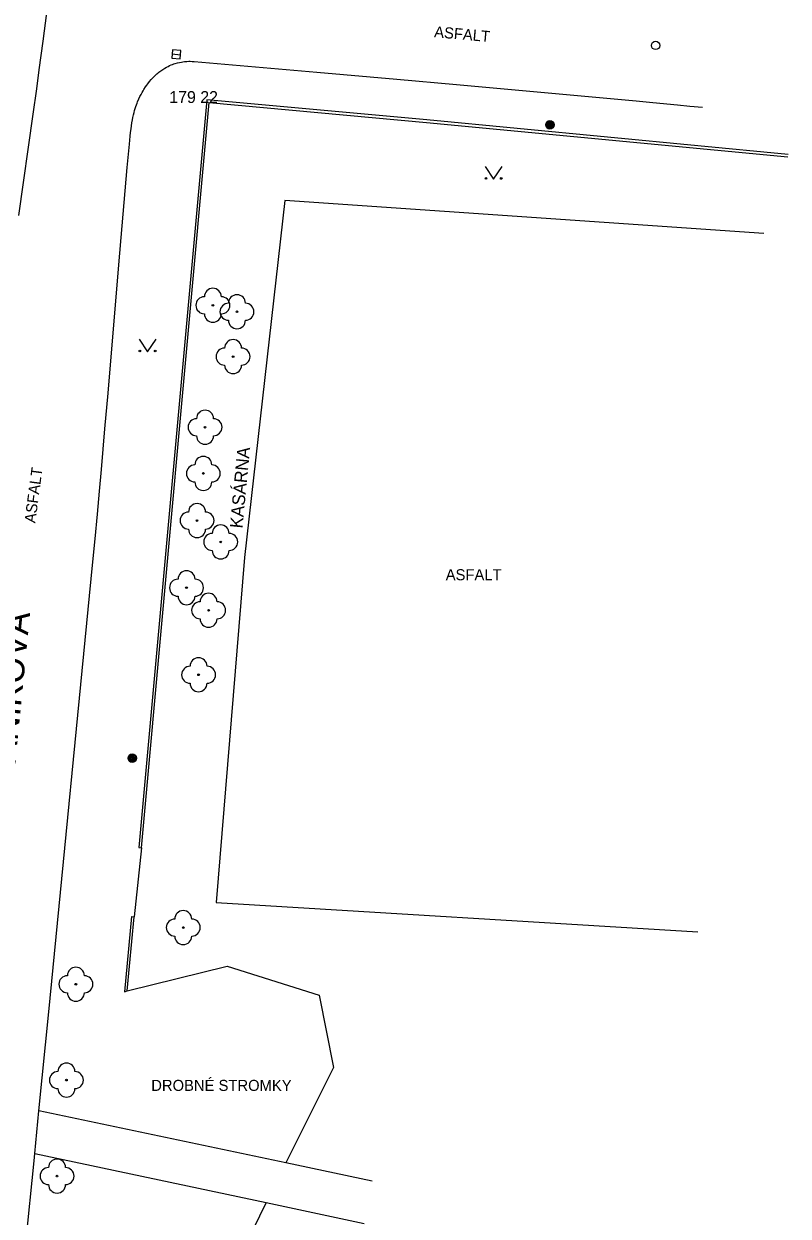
# Model space of a CAD drawing. Extents: x -538441 to -536770, y -1181008 to -1179809.
# Drawn here: x -537087.2 to -537042.3, y -1180849.4 to -1180779.3 of the extents above; entities that cross this region are included whole.
import ezdxf

# ---------------------------------------------------------------- set-up
doc = ezdxf.new("R2010")
doc.units = 0
for name, color, linetype in [('Vrstva 10', 7, 'Continuous'), ('Vrstva 11', 7, 'Continuous'), ('Vrstva 21', 7, 'Continuous'), ('Vrstva 22', 7, 'Continuous'), ('Vrstva 25', 7, 'Continuous'), ('Vrstva 27', 7, 'Continuous'), ('Vrstva 28', 7, 'Continuous'), ('Vrstva 36', 7, 'Continuous'), ('Vrstva 4', 7, 'Continuous'), ('Vrstva 40', 7, 'Continuous'), ('Vrstva 41', 7, 'Continuous'), ('Vrstva 49', 7, 'Continuous'), ('Vrstva 7', 7, 'Continuous'), ('Vrstva 8', 7, 'Continuous')]:
    doc.layers.add(name, color=color, linetype=linetype)

msp = doc.modelspace()

# ---------------------------------------------------------------- linework, layer by layer
at = {"layer": 'Vrstva 10'}
for p, q in [((-537073.585, -1180781.803), (-537069.981, -1180782.118)), ((-537061.759, -1180782.852), (-537051.19, -1180783.81)), ((-537087.518, -1180790.548), (-537086.674, -1180784.586)), ((-537082.266, -1180801.001), (-537081.65, -1180793.68)), ((-537082.445, -1180803.092), (-537082.266, -1180801.001)), ((-537085.756, -1180837.388), (-537083.18, -1180811.11)), ((-537087.117, -1180851.151), (-537086.62, -1180846.146))]:
    msp.add_line(p, q, dxfattribs=at)
for points in [[(-537086.674, -1180784.586), (-537086.465, -1180783.095), (-537086.31, -1180781.977), (-537086.082, -1180780.299), (-537085.86, -1180778.62)], [(-537080.526, -1180783.859), (-537080.455, -1180783.693), (-537080.387, -1180783.548), (-537080.322, -1180783.421), (-537080.261, -1180783.311), (-537080.205, -1180783.215), (-537080.153, -1180783.131), (-537080.057, -1180782.985), (-537079.98, -1180782.875), (-537079.919, -1180782.794), (-537079.822, -1180782.672), (-537079.72, -1180782.55), (-537079.653, -1180782.475), (-537079.587, -1180782.405), (-537079.521, -1180782.339), (-537079.458, -1180782.278), (-537079.395, -1180782.222), (-537079.333, -1180782.169), (-537079.273, -1180782.119), (-537079.154, -1180782.029), (-537079.041, -1180781.951), (-537078.934, -1180781.884), (-537078.831, -1180781.826), (-537078.734, -1180781.775), (-537078.642, -1180781.731), (-537078.555, -1180781.694), (-537078.473, -1180781.661), (-537078.395, -1180781.633), (-537078.322, -1180781.609), (-537078.183, -1180781.57), (-537078.061, -1180781.541), (-537077.954, -1180781.521), (-537077.859, -1180781.506), (-537077.776, -1180781.496), (-537077.63, -1180781.484), (-537077.521, -1180781.479), (-537077.438, -1180781.478), (-537077.314, -1180781.482), (-537077.19, -1180781.49), (-537073.585, -1180781.803)], [(-537069.981, -1180782.118), (-537065.283, -1180782.535), (-537061.759, -1180782.852)], [(-537081.65, -1180793.68), (-537081.495, -1180791.85), (-537081.257, -1180789.105), (-537081.135, -1180787.732), (-537081.01, -1180786.36), (-537080.987, -1180786.11), (-537080.964, -1180785.878), (-537080.94, -1180785.66), (-537080.915, -1180785.458), (-537080.889, -1180785.269), (-537080.861, -1180785.093), (-537080.831, -1180784.928), (-537080.801, -1180784.775), (-537080.768, -1180784.631), (-537080.735, -1180784.497), (-537080.701, -1180784.372), (-537080.666, -1180784.255), (-537080.631, -1180784.146), (-537080.596, -1180784.044), (-537080.561, -1180783.949), (-537080.526, -1180783.859)], [(-537051.19, -1180783.81), (-537050.218, -1180783.902), (-537048.759, -1180784.043), (-537048.03, -1180784.11), (-537047.3, -1180784.17)], [(-537083.18, -1180811.11), (-537083.03, -1180809.564), (-537082.894, -1180808.115), (-537082.769, -1180806.756), (-537082.655, -1180805.482), (-537082.445, -1180803.092)], [(-537086.62, -1180846.146), (-537086.578, -1180845.724), (-537086.33, -1180843.208), (-537085.756, -1180837.388)]]:
    msp.add_lwpolyline(points, dxfattribs=at)
at = {"layer": 'Vrstva 11'}
for p, q in [((-537071.86, -1180789.67), (-537074.24, -1180810.67)), ((-537043.68, -1180791.6), (-537071.86, -1180789.67)), ((-537074.24, -1180810.67), (-537075.91, -1180830.96)), ((-537075.91, -1180830.96), (-537047.56, -1180832.69))]:
    msp.add_line(p, q, dxfattribs=at)
for points in [[(-537066.72, -1180847.35), (-537071.798, -1180846.277), (-537086.33, -1180843.208)], [(-537086.578, -1180845.724), (-537072.957, -1180848.609), (-537067.19, -1180849.83)]]:
    msp.add_lwpolyline(points, dxfattribs=at)
at = {"layer": 'Vrstva 21'}
for p, q in [((-537081.148, -1180836.157), (-537075.25, -1180834.71)), ((-537075.25, -1180834.71), (-537069.84, -1180836.4)), ((-537069.84, -1180836.4), (-537069.01, -1180840.67)), ((-537069.01, -1180840.67), (-537071.798, -1180846.277)), ((-537072.957, -1180848.609), (-537078.12, -1180858.99))]:
    msp.add_line(p, q, dxfattribs=at)
at = {"layer": 'Vrstva 22'}
for centre in [(-537076.1, -1180795.83), (-537074.68, -1180796.21), (-537074.91, -1180798.85), (-537076.56, -1180803), (-537076.66, -1180805.72), (-537077.03, -1180808.49), (-537075.64, -1180809.75), (-537077.65, -1180812.44), (-537076.35, -1180813.77), (-537076.94, -1180817.56), (-537077.84, -1180832.43), (-537084.16, -1180835.76), (-537084.713, -1180841.403), (-537085.267, -1180847.047)]:
    msp.add_circle(centre, 0.05, dxfattribs=at)
for centre, start, end in [((-537076.1, -1180795.33), 0, 180), ((-537076.6, -1180795.83), 90, 270), ((-537075.6, -1180795.83), 270, 90), ((-537074.68, -1180795.71), 0, 180), ((-537075.18, -1180796.21), 90, 270), ((-537074.18, -1180796.21), 270, 90), ((-537076.1, -1180796.33), 180, 0), ((-537074.68, -1180796.71), 180, 0), ((-537075.41, -1180798.85), 90, 270), ((-537074.91, -1180798.35), 0, 180), ((-537074.41, -1180798.85), 270, 90), ((-537074.91, -1180799.35), 180, 0), ((-537077.06, -1180803), 90, 270), ((-537076.56, -1180802.5), 0, 180), ((-537076.06, -1180803), 270, 90), ((-537076.56, -1180803.5), 180, 0), ((-537077.16, -1180805.72), 90, 270), ((-537076.66, -1180805.22), 0, 180), ((-537076.16, -1180805.72), 270, 90), ((-537076.66, -1180806.22), 180, 0), ((-537077.03, -1180807.99), 0, 180), ((-537077.53, -1180808.49), 90, 270), ((-537076.53, -1180808.49), 270, 90), ((-537075.64, -1180809.25), 0, 180), ((-537077.03, -1180808.99), 180, 0), ((-537076.14, -1180809.75), 90, 270), ((-537075.14, -1180809.75), 270, 90), ((-537075.64, -1180810.25), 180, 0), ((-537077.65, -1180811.94), 0, 180), ((-537078.15, -1180812.44), 90, 270), ((-537077.15, -1180812.44), 270, 90), ((-537077.65, -1180812.94), 180, 0), ((-537076.35, -1180813.27), 0, 180), ((-537076.85, -1180813.77), 90, 270), ((-537075.85, -1180813.77), 270, 90), ((-537076.35, -1180814.27), 180, 0), ((-537076.94, -1180817.06), 0, 180), ((-537077.44, -1180817.56), 90, 270), ((-537076.44, -1180817.56), 270, 90), ((-537076.94, -1180818.06), 180, 0), ((-537078.34, -1180832.43), 90, 270), ((-537077.84, -1180831.93), 0, 180), ((-537077.34, -1180832.43), 270, 90), ((-537077.84, -1180832.93), 180, 0), ((-537084.16, -1180835.26), 0, 180), ((-537084.66, -1180835.76), 90, 270), ((-537083.66, -1180835.76), 270, 90), ((-537084.16, -1180836.26), 180, 0), ((-537084.713, -1180840.903), 0, 180), ((-537085.213, -1180841.403), 90, 270), ((-537084.213, -1180841.403), 270, 90), ((-537084.713, -1180841.903), 180, 0), ((-537085.267, -1180846.547), 0, 180), ((-537085.767, -1180847.047), 90, 270), ((-537084.767, -1180847.047), 270, 90), ((-537085.267, -1180847.547), 180, 0)]:
    msp.add_arc(centre, 0.5, start, end, dxfattribs=at)
at = {"layer": 'Vrstva 25'}
for centre, radius in [((-537056.27, -1180785.21), 0.25), ((-537056.27, -1180785.21), 0.2), ((-537056.27, -1180785.21), 0.15), ((-537056.27, -1180785.21), 0.1), ((-537056.27, -1180785.21), 0.05), ((-537080.84, -1180822.47), 0.25), ((-537080.84, -1180822.47), 0.2), ((-537080.84, -1180822.47), 0.15), ((-537080.84, -1180822.47), 0.1), ((-537080.84, -1180822.47), 0.05)]:
    msp.add_circle(centre, radius, dxfattribs=at)
at = {"layer": 'Vrstva 27'}
msp.add_line((-537078.499, -1180781.048), (-537078.001, -1180781.092), dxfattribs=at)
msp.add_lwpolyline([(-537078.521, -1180781.297), (-537078.023, -1180781.341), (-537077.979, -1180780.843), (-537078.477, -1180780.799)], close=True, dxfattribs=at)
at = {"layer": 'Vrstva 28'}
msp.add_circle((-537050.05, -1180780.54), 0.25, dxfattribs=at)
at = {"layer": 'Vrstva 36'}
for points in [[(-537060.084, -1180787.667), (-537059.584, -1180788.417), (-537059.084, -1180787.667)], [(-537080.441, -1180797.817), (-537079.941, -1180798.567), (-537079.441, -1180797.817)]]:
    msp.add_lwpolyline(points, dxfattribs=at)
for centre in [(-537060.034, -1180788.367), (-537059.135, -1180788.367), (-537080.391, -1180798.517), (-537079.492, -1180798.517)]:
    msp.add_circle(centre, 0.05, dxfattribs=at)
at = {"layer": 'Vrstva 7'}
for p, q in [((-537076.445, -1180783.746), (-537080.449, -1180827.726)), ((-537080.3, -1180827.74), (-537076.31, -1180783.91)), ((-537063.515, -1180784.92), (-537076.445, -1180783.746)), ((-537076.31, -1180783.91), (-537063.53, -1180785.07)), ((-537042.255, -1180786.95), (-537063.515, -1180784.92)), ((-537063.53, -1180785.07), (-537042.27, -1180787.1)), ((-537080.449, -1180827.726), (-537080.3, -1180827.74)), ((-537081.148, -1180836.157), (-537080.73, -1180831.79)), ((-537080.879, -1180831.775), (-537080.73, -1180831.79))]:
    msp.add_line(p, q, dxfattribs=at)
msp.add_lwpolyline([(-537080.879, -1180831.775), (-537081.294, -1180836.201), (-537081.148, -1180836.157)], dxfattribs=at)
at = {"layer": 'Vrstva 8'}
msp.add_line((-537080.3, -1180827.74), (-537080.73, -1180831.79), dxfattribs=at)

# ---------------------------------------------------------------- texts
at = {"layer": 'Vrstva 4'}
msp.add_text('179 22 ', height=0.7, dxfattribs=at).set_placement((-537078.663, -1180783.93))
at = {"layer": 'Vrstva 40'}
for rotation, p in [(354.85222, (-537063.098, -1180780.055)), (82.44195, (-537086.547, -1180808.663))]:
    msp.add_text('ASFALT', height=0.65, rotation=rotation, dxfattribs=at).set_placement(p)
for s, p in [('ASFALT', (-537062.4, -1180812)), ('DROBNÉ STROMKY', (-537079.724, -1180842.038))]:
    msp.add_text(s, height=0.65, dxfattribs=at).set_placement(p)
at = {"layer": 'Vrstva 41'}
msp.add_text('KASÁRNA', height=0.75, rotation=84.48622, dxfattribs=at).set_placement((-537074.363, -1180808.972))
at = {"layer": 'Vrstva 49'}
msp.add_text('ul. ŠTEFÁNIKOVA', height=1.5, rotation=84.41001, dxfattribs=at).set_placement((-537088.478, -1180830.562))

doc.saveas('drawing.dxf')
